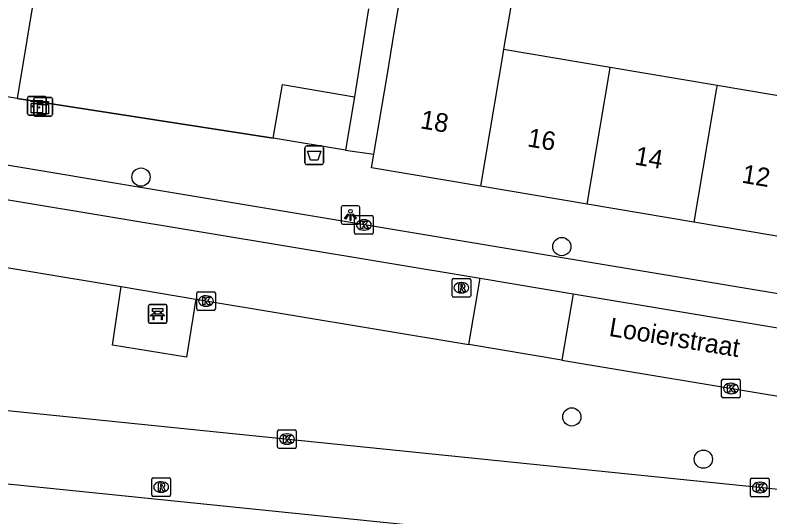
# Model space of a CAD drawing. Extents: x 160861 to 161308, y 384024 to 384878.
# Drawn here: x 161153.6 to 161194.13, y 384677.68 to 384704.61 of the extents above; entities that cross this region are included whole.
import ezdxf

# ---------------------------------------------------------------- set-up
doc = ezdxf.new("R2010")
doc.units = 0
for name, color, linetype in [('IMGEO_Afvalbak', 7, 'Continuous'), ('IMGEO_Bank', 7, 'Continuous'), ('IMGEO_Boom', 7, 'Continuous'), ('IMGEO_Groenvoorziening', 7, 'Continuous'), ('IMGEO_Kast', 7, 'Continuous'), ('IMGEO_Kolk', 7, 'Continuous'), ('IMGEO_Lichtpunt', 7, 'Continuous'), ('IMGEO_Muur', 7, 'Continuous'), ('IMGEO_Openbare_ruimte_label', 7, 'Continuous'), ('IMGEO_Pand', 7, 'Continuous'), ('IMGEO_Pand_nummerreeks', 7, 'Continuous'), ('IMGEO_Rijbaan_lokaal_open', 7, 'Continuous'), ('IMGEO_Rioolput', 7, 'Continuous'), ('IMGEO_Voetpad_open', 7, 'Continuous')]:
    doc.layers.add(name, color=color, linetype=linetype)

msp = doc.modelspace()

# ---------------------------------------------------------------- linework, layer by layer
at = {"layer": 'IMGEO_Afvalbak'}
for p, q in [((161169.166, 384696.687), (161169.166, 384697.487)), ((161169.166, 384697.487), (161169.166, 384696.687)), ((161169.266, 384697.587), (161170.056, 384697.587)), ((161170.056, 384697.587), (161169.266, 384697.587)), ((161170.156, 384697.487), (161170.156, 384696.687)), ((161170.156, 384696.687), (161170.156, 384697.487)), ((161170.056, 384696.587), (161169.266, 384696.587)), ((161169.266, 384696.587), (161170.056, 384696.587))]:
    msp.add_line(p, q, dxfattribs=at)
msp.add_lwpolyline([(161169.309, 384697.301), (161170.013, 384697.301), (161169.864, 384696.831), (161169.458, 384696.831), (161169.309, 384697.301)], dxfattribs=at)
for centre, start, end in [((161169.266, 384697.487), 90, 180), ((161169.266, 384697.487), 90, 180), ((161170.056, 384697.487), 0, 90), ((161170.056, 384697.487), 360, 90), ((161169.266, 384696.687), 180, 270), ((161169.266, 384696.687), 180, 270), ((161170.056, 384696.687), 270, 0), ((161170.056, 384696.687), 270, 0)]:
    msp.add_arc(centre, 0.1, start, end, dxfattribs=at)
at = {"layer": 'IMGEO_Bank'}
for p, q in [((161160.754, 384688.154), (161160.754, 384688.995)), ((161160.754, 384688.995), (161160.754, 384688.154)), ((161160.829, 384689.079), (161161.67, 384689.079)), ((161161.67, 384689.079), (161160.829, 384689.079)), ((161161.754, 384689.004), (161161.754, 384688.163)), ((161161.754, 384688.163), (161161.754, 384689.004)), ((161161.451, 384688.477), (161161.058, 384688.477)), ((161161.063, 384688.585), (161161.063, 384688.691)), ((161161.107, 384688.691), (161161.107, 384688.585)), ((161161.395, 384688.697), (161161.113, 384688.697)), ((161161.113, 384688.579), (161161.395, 384688.579)), ((161161.401, 384688.585), (161161.401, 384688.691)), ((161161.445, 384688.691), (161161.445, 384688.585)), ((161161.679, 384688.079), (161160.838, 384688.079)), ((161160.838, 384688.079), (161161.679, 384688.079))]:
    msp.add_line(p, q, dxfattribs=at)
for points in [[(161161.057, 384688.697), (161160.971, 384688.697), (161160.971, 384688.858), (161161.534, 384688.858), (161161.534, 384688.697), (161161.451, 384688.697)], [(161161.001, 384688.477), (161160.859, 384688.477), (161160.971, 384688.579), (161161.057, 384688.579)], [(161161.051, 384688.47), (161161.051, 384688.263), (161161.008, 384688.263), (161161.008, 384688.47)], [(161161.451, 384688.579), (161161.534, 384688.579), (161161.646, 384688.477), (161161.507, 384688.477)], [(161161.501, 384688.47), (161161.501, 384688.263), (161161.457, 384688.263), (161161.457, 384688.47)]]:
    msp.add_lwpolyline(points, dxfattribs=at)
for centre, radius, start, end in [((161160.832, 384689.001), 0.0779, 92.4484, 184.2845), ((161160.832, 384689.001), 0.0779, 92.4484, 184.2845), ((161161.676, 384689.001), 0.0779, 2.4484, 94.2845), ((161161.676, 384689.001), 0.0779, 2.4484, 94.2845), ((161161.001, 384688.47), 0.00671, 2.8957, 87.1043), ((161161.058, 384688.47), 0.00671, 92.8957, 177.1043), ((161161.056, 384688.69), 0.00671, 2.8957, 87.1043), ((161161.056, 384688.586), 0.00671, 272.8957, 357.1043), ((161161.113, 384688.69), 0.00671, 92.8957, 177.1043), ((161161.113, 384688.586), 0.00671, 182.8957, 267.1043), ((161161.395, 384688.69), 0.00671, 2.8957, 87.1043), ((161161.395, 384688.586), 0.00671, 272.8957, 357.1043), ((161161.452, 384688.69), 0.00671, 92.8957, 177.1043), ((161161.452, 384688.586), 0.00671, 182.8957, 267.1043), ((161161.45, 384688.47), 0.00671, 2.8957, 87.1043), ((161161.507, 384688.47), 0.00671, 92.8957, 177.1043), ((161160.832, 384688.157), 0.0779, 182.4484, 274.2845), ((161160.832, 384688.157), 0.0779, 182.4484, 274.2845), ((161161.676, 384688.157), 0.0779, 272.4484, 4.2845), ((161161.676, 384688.157), 0.0779, 272.4484, 4.2845)]:
    msp.add_arc(centre, radius, start, end, dxfattribs=at)
at = {"layer": 'IMGEO_Boom'}
for centre in [(161160.36, 384695.918), (161182.958, 384692.189), (161183.493, 384683.049), (161190.558, 384680.779)]:
    msp.add_circle(centre, 0.489, dxfattribs=at)
at = {"layer": 'IMGEO_Groenvoorziening'}
msp.add_lwpolyline([(161163.306, 384689.368), (161162.797, 384686.255), (161158.825, 384686.907), (161159.285, 384690.038)], dxfattribs=at)
at = {"layer": 'IMGEO_Kast'}
for p, q in [((161154.27, 384699.321), (161154.27, 384700.162)), ((161154.27, 384700.162), (161154.27, 384699.321)), ((161154.345, 384700.246), (161155.186, 384700.246)), ((161155.186, 384700.246), (161154.345, 384700.246)), ((161154.675, 384700.19), (161155.516, 384700.19)), ((161155.516, 384700.19), (161154.675, 384700.19)), ((161155.27, 384700.171), (161155.27, 384699.33)), ((161155.27, 384699.33), (161155.27, 384700.171)), ((161154.6, 384699.265), (161154.6, 384700.106)), ((161154.6, 384700.106), (161154.6, 384699.265)), ((161155.6, 384700.115), (161155.6, 384699.274)), ((161155.6, 384699.274), (161155.6, 384700.115)), ((161155.195, 384699.246), (161154.354, 384699.246)), ((161154.354, 384699.246), (161155.195, 384699.246)), ((161155.525, 384699.19), (161154.684, 384699.19)), ((161154.684, 384699.19), (161155.525, 384699.19))]:
    msp.add_line(p, q, dxfattribs=at)
for points in [[(161154.465, 384700.036), (161155.065, 384700.036), (161155.065, 384699.951), (161154.465, 384699.951), (161154.465, 384700.036)], [(161154.465, 384699.861), (161155.065, 384699.861), (161155.065, 384699.372), (161154.465, 384699.372), (161154.465, 384699.861)], [(161154.795, 384699.98), (161155.395, 384699.98), (161155.395, 384699.895), (161154.795, 384699.895), (161154.795, 384699.98)], [(161154.795, 384699.805), (161155.395, 384699.805), (161155.395, 384699.316), (161154.795, 384699.316), (161154.795, 384699.805)]]:
    msp.add_lwpolyline(points, dxfattribs=at)
for centre in [(161154.549, 384699.71), (161154.879, 384699.654)]:
    msp.add_circle(centre, 0.0377, dxfattribs=at)
for centre, start, end in [((161154.348, 384700.168), 92.4484, 184.2845), ((161154.348, 384700.168), 92.4484, 184.2845), ((161154.678, 384700.112), 92.4484, 184.2845), ((161154.678, 384700.112), 92.4484, 184.2845), ((161155.192, 384700.168), 2.4484, 94.2845), ((161155.192, 384700.168), 2.4484, 94.2845), ((161155.522, 384700.112), 2.4484, 94.2845), ((161155.522, 384700.112), 2.4484, 94.2845), ((161154.348, 384699.324), 182.4484, 274.2845), ((161154.348, 384699.324), 182.4484, 274.2845), ((161155.192, 384699.324), 272.4484, 4.2845), ((161155.192, 384699.324), 272.4484, 4.2845), ((161154.678, 384699.268), 182.4484, 274.2845), ((161154.678, 384699.268), 182.4484, 274.2845), ((161155.522, 384699.268), 272.4484, 4.2845), ((161155.522, 384699.268), 272.4484, 4.2845)]:
    msp.add_arc(centre, 0.0779, start, end, dxfattribs=at)
at = {"layer": 'IMGEO_Kolk'}
for p, q in [((161171.826, 384692.925), (161171.826, 384693.777)), ((161171.901, 384693.851), (161172.753, 384693.851)), ((161172.827, 384693.777), (161172.827, 384692.925)), ((161172.314, 384693.631), (161172.339, 384693.631)), ((161172.753, 384692.851), (161171.901, 384692.851)), ((161172.337, 384693.071), (161172.312, 384693.071)), ((161163.35, 384688.841), (161163.35, 384689.693)), ((161163.425, 384689.767), (161164.277, 384689.767)), ((161164.351, 384689.693), (161164.351, 384688.841)), ((161163.838, 384689.547), (161163.863, 384689.547)), ((161163.861, 384688.987), (161163.836, 384688.987)), ((161164.277, 384688.767), (161163.425, 384688.767)), ((161191.54, 384684.147), (161191.54, 384684.999)), ((161191.615, 384685.073), (161192.467, 384685.073)), ((161192.028, 384684.853), (161192.053, 384684.853)), ((161192.541, 384684.999), (161192.541, 384684.147)), ((161192.467, 384684.073), (161191.615, 384684.073)), ((161192.051, 384684.293), (161192.026, 384684.293)), ((161167.769, 384682.358), (161168.621, 384682.358)), ((161167.694, 384681.432), (161167.694, 384682.284)), ((161168.182, 384682.138), (161168.207, 384682.138)), ((161168.695, 384682.284), (161168.695, 384681.432)), ((161168.205, 384681.578), (161168.18, 384681.578)), ((161168.621, 384681.358), (161167.769, 384681.358)), ((161193.091, 384678.835), (161193.091, 384679.687)), ((161193.166, 384679.761), (161194.018, 384679.761)), ((161193.579, 384679.541), (161193.604, 384679.541)), ((161194.092, 384679.687), (161194.092, 384678.835)), ((161194.018, 384678.761), (161193.166, 384678.761)), ((161193.602, 384678.981), (161193.577, 384678.981))]:
    msp.add_line(p, q, dxfattribs=at)
for points in [[(161171.826, 384692.925), (161171.826, 384693.777)], [(161171.901, 384693.851), (161172.753, 384693.851)], [(161172.827, 384693.777), (161172.827, 384692.925)], [(161172.147, 384693.551), (161172.27, 384693.551), (161172.27, 384693.4), (161172.4, 384693.551), (161172.564, 384693.551), (161172.418, 384693.4), (161172.571, 384693.151), (161172.419, 384693.151), (161172.334, 384693.315), (161172.27, 384693.248), (161172.27, 384693.151), (161172.147, 384693.151), (161172.147, 384693.551)], [(161172.753, 384692.851), (161171.901, 384692.851)], [(161163.35, 384688.841), (161163.35, 384689.693)], [(161163.425, 384689.767), (161164.277, 384689.767)], [(161164.351, 384689.693), (161164.351, 384688.841)], [(161163.671, 384689.467), (161163.794, 384689.467), (161163.794, 384689.316), (161163.924, 384689.467), (161164.088, 384689.467), (161163.942, 384689.316), (161164.095, 384689.067), (161163.943, 384689.067), (161163.858, 384689.231), (161163.794, 384689.164), (161163.794, 384689.067), (161163.671, 384689.067), (161163.671, 384689.467)], [(161164.277, 384688.767), (161163.425, 384688.767)], [(161191.54, 384684.147), (161191.54, 384684.999)], [(161191.615, 384685.073), (161192.467, 384685.073)], [(161191.861, 384684.773), (161191.984, 384684.773), (161191.984, 384684.622), (161192.114, 384684.773), (161192.278, 384684.773), (161192.132, 384684.622), (161192.285, 384684.373), (161192.133, 384684.373), (161192.048, 384684.537), (161191.984, 384684.47), (161191.984, 384684.373), (161191.861, 384684.373), (161191.861, 384684.773)], [(161192.541, 384684.999), (161192.541, 384684.147)], [(161192.467, 384684.073), (161191.615, 384684.073)], [(161167.769, 384682.358), (161168.621, 384682.358)], [(161167.694, 384681.432), (161167.694, 384682.284)], [(161168.015, 384682.058), (161168.138, 384682.058), (161168.138, 384681.907), (161168.268, 384682.058), (161168.432, 384682.058), (161168.286, 384681.907), (161168.439, 384681.658), (161168.287, 384681.658), (161168.202, 384681.822), (161168.138, 384681.755), (161168.138, 384681.658), (161168.015, 384681.658), (161168.015, 384682.058)], [(161168.695, 384682.284), (161168.695, 384681.432)], [(161168.621, 384681.358), (161167.769, 384681.358)], [(161193.091, 384678.835), (161193.091, 384679.687)], [(161193.166, 384679.761), (161194.018, 384679.761)], [(161193.412, 384679.461), (161193.535, 384679.461), (161193.535, 384679.31), (161193.665, 384679.461), (161193.829, 384679.461), (161193.683, 384679.31), (161193.836, 384679.061), (161193.684, 384679.061), (161193.599, 384679.225), (161193.535, 384679.158), (161193.535, 384679.061), (161193.412, 384679.061), (161193.412, 384679.461)], [(161194.092, 384679.687), (161194.092, 384678.835)], [(161194.018, 384678.761), (161193.166, 384678.761)]]:
    msp.add_lwpolyline(points, dxfattribs=at)
for centre, start, end in [((161171.903, 384693.775), 91.552, 178.448), ((161171.903, 384693.775), 91.552, 178.448), ((161172.751, 384693.775), 1.552, 88.448), ((161172.751, 384693.775), 1.552, 88.448), ((161171.903, 384692.927), 181.552, 268.448), ((161171.903, 384692.927), 181.552, 268.448), ((161172.751, 384692.927), 271.552, 358.448), ((161172.751, 384692.927), 271.552, 358.448), ((161163.427, 384689.691), 91.552, 178.448), ((161163.427, 384689.691), 91.552, 178.448), ((161164.275, 384689.691), 1.552, 88.448), ((161164.275, 384689.691), 1.552, 88.448), ((161163.427, 384688.843), 181.552, 268.448), ((161163.427, 384688.843), 181.552, 268.448), ((161164.275, 384688.843), 271.552, 358.448), ((161164.275, 384688.843), 271.552, 358.448), ((161191.617, 384684.997), 91.552, 178.448), ((161191.617, 384684.997), 91.552, 178.448), ((161192.465, 384684.997), 1.552, 88.448), ((161192.465, 384684.997), 1.552, 88.448), ((161191.617, 384684.149), 181.552, 268.448), ((161191.617, 384684.149), 181.552, 268.448), ((161192.465, 384684.149), 271.552, 358.448), ((161192.465, 384684.149), 271.552, 358.448), ((161167.771, 384682.282), 91.552, 178.448), ((161167.771, 384682.282), 91.552, 178.448), ((161168.619, 384682.282), 1.552, 88.448), ((161168.619, 384682.282), 1.552, 88.448), ((161167.771, 384681.434), 181.552, 268.448), ((161167.771, 384681.434), 181.552, 268.448), ((161168.619, 384681.434), 271.552, 358.448), ((161168.619, 384681.434), 271.552, 358.448), ((161193.168, 384679.685), 91.552, 178.448), ((161193.168, 384679.685), 91.552, 178.448), ((161194.016, 384679.685), 1.552, 88.448), ((161194.016, 384679.685), 1.552, 88.448), ((161193.168, 384678.837), 181.552, 268.448), ((161193.168, 384678.837), 181.552, 268.448), ((161194.016, 384678.837), 271.552, 358.448), ((161194.016, 384678.837), 271.552, 358.448)]:
    msp.add_arc(centre, 0.0765, start, end, dxfattribs=at)
for centre, major_axis, ratio, start_param, end_param in [((161172.313, 384693.351), (-0.387, 0.002), 0.722429, 4.712389, 7.853982), ((161172.338, 384693.351), (-0.39, 0.002), 0.717154, 1.570796, 4.712389), ((161163.837, 384689.267), (-0.387, 0.002), 0.722429, 4.712389, 7.853982), ((161163.862, 384689.267), (-0.39, 0.002), 0.717154, 1.570796, 4.712389), ((161192.027, 384684.573), (-0.387, 0.002), 0.722429, 4.712389, 7.853982), ((161192.052, 384684.573), (-0.39, 0.002), 0.717154, 1.570796, 4.712389), ((161168.181, 384681.858), (-0.387, 0.002), 0.722429, 4.712389, 7.853982), ((161168.206, 384681.858), (-0.39, 0.002), 0.717154, 1.570796, 4.712389), ((161193.578, 384679.261), (-0.387, 0.002), 0.722429, 4.712389, 7.853982), ((161193.603, 384679.261), (-0.39, 0.002), 0.717154, 1.570796, 4.712389)]:
    msp.add_ellipse(centre, major_axis=major_axis, ratio=ratio, start_param=start_param, end_param=end_param, dxfattribs=at)
at = {"layer": 'IMGEO_Lichtpunt'}
for p, q in [((161171.108, 384694.286), (161171.108, 384693.479)), ((161171.108, 384694.286), (161171.108, 384693.479)), ((161172.01, 384694.381), (161171.202, 384694.381)), ((161172.01, 384694.381), (161171.202, 384694.381)), ((161172.104, 384693.479), (161172.104, 384694.286)), ((161172.104, 384693.479), (161172.104, 384694.286)), ((161171.202, 384693.385), (161172.01, 384693.385)), ((161171.202, 384693.385), (161172.01, 384693.385))]:
    msp.add_line(p, q, dxfattribs=at)
for points in [[(161171.482, 384693.95), (161171.521, 384693.922), (161171.333, 384693.66), (161171.295, 384693.687), (161171.482, 384693.95)], [(161171.584, 384693.902), (161171.631, 384693.902), (161171.631, 384693.58), (161171.584, 384693.58), (161171.584, 384693.902)], [(161171.694, 384693.922), (161171.732, 384693.949), (161171.919, 384693.687), (161171.88, 384693.659), (161171.694, 384693.922)]]:
    msp.add_lwpolyline(points, dxfattribs=at)
msp.add_circle((161171.607, 384694.084), 0.0994, dxfattribs=at)
for centre, start, end in [((161171.202, 384694.286), 90, 180), ((161171.202, 384694.286), 90, 180), ((161172.01, 384694.286), 0, 90), ((161172.01, 384694.286), 0, 90), ((161171.202, 384693.479), 180, 270), ((161171.202, 384693.479), 180, 270), ((161172.01, 384693.479), 270, 0), ((161172.01, 384693.479), 270, 360)]:
    msp.add_arc(centre, 0.0946, start, end, dxfattribs=at)
at = {"layer": 'IMGEO_Muur'}
msp.add_lwpolyline([(161153.7, 384700.13), (161167.463, 384698.012)], dxfattribs=at)
at = {"layer": 'IMGEO_Pand'}
for points in [[(161172.859, 384697.147), (161173.571, 384701.354), (161173.98, 384703.776), (161174.476, 384706.71)], [(161174.476, 384706.71), (161180.326, 384705.721), (161179.83, 384702.787)], [(161154.738, 384706.42), (161153.7, 384700.13)], [(161179.83, 384702.787), (161179.787, 384702.533), (161178.587, 384695.434)], [(161179.83, 384702.787), (161185.562, 384701.818)], [(161184.319, 384694.465), (161185.519, 384701.564), (161185.562, 384701.818)], [(161185.562, 384701.818), (161191.294, 384700.85)], [(161153.7, 384700.13), (161146.719, 384701.281)], [(161167.463, 384698.012), (161167.949, 384700.888), (161171.82, 384700.234)], [(161191.294, 384700.85), (161191.251, 384700.595), (161190.051, 384693.497)], [(161191.294, 384700.85), (161197.026, 384699.881)], [(161171.82, 384700.234), (161171.334, 384697.358)], [(161171.334, 384697.358), (161167.463, 384698.012)], [(161178.587, 384695.434), (161172.737, 384696.423), (161172.859, 384697.147)], [(161184.319, 384694.465), (161178.587, 384695.434)], [(161190.051, 384693.497), (161184.319, 384694.465)], [(161195.783, 384692.528), (161190.051, 384693.497)]]:
    msp.add_lwpolyline(points, dxfattribs=at)
at = {"layer": 'IMGEO_Rijbaan_lokaal_open'}
for points in [[(161143.528, 384696.307), (161178.569, 384690.489)], [(161144.71, 384692.468), (161144.834, 384692.446), (161159.285, 384690.038)], [(161177.965, 384686.926), (161178.569, 384690.489)], [(161178.569, 384690.489), (161183.564, 384689.645)], [(161159.285, 384690.038), (161163.306, 384689.368)], [(161183.564, 384689.645), (161182.965, 384686.099)], [(161183.564, 384689.645), (161225.466, 384682.697)], [(161163.306, 384689.368), (161177.965, 384686.926)], [(161182.965, 384686.099), (161177.965, 384686.926)], [(161182.965, 384686.099), (161195.22, 384684.061)], [(161194.533, 384679.161), (161194.415, 384679.172), (161147.028, 384683.998), (161144.055, 384684.484), (161143.417, 384684.619), (161143.107, 384684.751)], [(161143.188, 384680.479), (161185.816, 384676.135)]]:
    msp.add_lwpolyline(points, dxfattribs=at)
at = {"layer": 'IMGEO_Rioolput'}
for p, q in [((161177.065, 384689.554), (161177.065, 384690.406)), ((161177.14, 384690.48), (161177.992, 384690.48)), ((161178.066, 384690.406), (161178.066, 384689.554)), ((161177.553, 384690.26), (161177.578, 384690.26)), ((161177.576, 384689.7), (161177.551, 384689.7)), ((161177.992, 384689.48), (161177.14, 384689.48)), ((161160.941, 384678.859), (161160.941, 384679.711)), ((161161.016, 384679.785), (161161.868, 384679.785)), ((161161.429, 384679.565), (161161.454, 384679.565)), ((161161.942, 384679.711), (161161.942, 384678.859)), ((161161.868, 384678.785), (161161.016, 384678.785)), ((161161.452, 384679.005), (161161.427, 384679.005))]:
    msp.add_line(p, q, dxfattribs=at)
for points in [[(161177.065, 384689.554), (161177.065, 384690.406)], [(161177.14, 384690.48), (161177.992, 384690.48)], [(161178.066, 384690.406), (161178.066, 384689.554)], [(161177.654, 384690.178), (161177.402, 384690.18), (161177.402, 384689.78)], [(161177.58, 384690.099), (161177.526, 384690.099), (161177.526, 384690.018)], [(161177.526, 384690.018), (161177.578, 384690.018)], [(161177.402, 384689.78), (161177.526, 384689.78), (161177.526, 384689.942), (161177.537, 384689.942)], [(161177.584, 384689.913), (161177.655, 384689.78), (161177.795, 384689.78), (161177.73, 384689.906)], [(161177.992, 384689.48), (161177.14, 384689.48)], [(161160.941, 384678.859), (161160.941, 384679.711)], [(161161.016, 384679.785), (161161.868, 384679.785)], [(161161.53, 384679.483), (161161.278, 384679.485), (161161.278, 384679.085)], [(161161.942, 384679.711), (161161.942, 384678.859)], [(161161.278, 384679.085), (161161.402, 384679.085), (161161.402, 384679.247), (161161.413, 384679.247)], [(161161.456, 384679.404), (161161.402, 384679.404), (161161.402, 384679.323)], [(161161.402, 384679.323), (161161.454, 384679.323)], [(161161.46, 384679.218), (161161.531, 384679.085), (161161.671, 384679.085), (161161.606, 384679.211)], [(161161.868, 384678.785), (161161.016, 384678.785)]]:
    msp.add_lwpolyline(points, dxfattribs=at)
for centre, radius, start, end in [((161177.142, 384690.404), 0.0765, 91.552, 178.448), ((161177.142, 384690.404), 0.0765, 91.552, 178.448), ((161177.99, 384690.404), 0.0765, 1.552, 88.448), ((161177.99, 384690.404), 0.0765, 1.552, 88.448), ((161177.562, 384690.207), 0.19, 274.7715, 282.9687), ((161177.586, 384690.003), 0.0964, 77.0061, 93.1865), ((161177.6, 384690.06), 0.0378, 276.6634, 79.6772), ((161177.653, 384690.068), 0.109, 350.3612, 89.416), ((161177.651, 384690.068), 0.112, 277.5842, 350.9817), ((161177.536, 384689.889), 0.0533, 26.0293, 88.6989), ((161177.635, 384689.853), 0.108, 29.5134, 73.7905), ((161177.142, 384689.556), 0.0765, 181.552, 268.448), ((161177.142, 384689.556), 0.0765, 181.552, 268.448), ((161177.99, 384689.556), 0.0765, 271.552, 358.448), ((161177.99, 384689.556), 0.0765, 271.552, 358.448), ((161161.018, 384679.709), 0.0765, 91.552, 178.448), ((161161.018, 384679.709), 0.0765, 91.552, 178.448), ((161161.529, 384679.373), 0.109, 350.3612, 89.416), ((161161.866, 384679.709), 0.0765, 1.552, 88.448), ((161161.866, 384679.709), 0.0765, 1.552, 88.448), ((161161.412, 384679.194), 0.0533, 26.0293, 88.6989), ((161161.438, 384679.512), 0.19, 274.7715, 282.9687), ((161161.462, 384679.308), 0.0964, 77.0061, 93.1865), ((161161.476, 384679.365), 0.0378, 276.6634, 79.6772), ((161161.527, 384679.373), 0.112, 277.5842, 350.9817), ((161161.511, 384679.158), 0.108, 29.5134, 73.7905), ((161161.018, 384678.861), 0.0765, 181.552, 268.448), ((161161.018, 384678.861), 0.0765, 181.552, 268.448), ((161161.866, 384678.861), 0.0765, 271.552, 358.448), ((161161.866, 384678.861), 0.0765, 271.552, 358.448)]:
    msp.add_arc(centre, radius, start, end, dxfattribs=at)
for centre, major_axis, ratio, start_param, end_param in [((161177.552, 384689.98), (-0.387, 0.002), 0.722429, 4.712389, 7.853982), ((161177.577, 384689.98), (-0.39, 0.002), 0.717154, 1.570796, 4.712389), ((161161.428, 384679.285), (-0.387, 0.002), 0.722429, 4.712389, 7.853982), ((161161.453, 384679.285), (-0.39, 0.002), 0.717154, 1.570796, 4.712389)]:
    msp.add_ellipse(centre, major_axis=major_axis, ratio=ratio, start_param=start_param, end_param=end_param, dxfattribs=at)
at = {"layer": 'IMGEO_Voetpad_open'}
for points in [[(161172.574, 384704.956), (161171.82, 384700.234)], [(161167.463, 384698.012), (161153.7, 384700.13)], [(161225.789, 384684.447), (161146.911, 384697.588)], [(161171.334, 384697.358), (161172.859, 384697.147)]]:
    msp.add_lwpolyline(points, dxfattribs=at)

# ---------------------------------------------------------------- texts
at = {"layer": 'IMGEO_Openbare_ruimte_label'}
msp.add_text('Looierstraat', height=1, rotation=350.6789, dxfattribs=at).set_placement((161185.452, 384687.399))
at = {"layer": 'IMGEO_Pand_nummerreeks'}
for s, p in [('18', (161175.313, 384698.543)), ('16', (161181.068, 384697.571)), ('14', (161186.827, 384696.597)), ('12', (161192.582, 384695.624))]:
    msp.add_text(s, height=1, rotation=350.4067, dxfattribs=at).set_placement(p)

doc.saveas('drawing.dxf')
